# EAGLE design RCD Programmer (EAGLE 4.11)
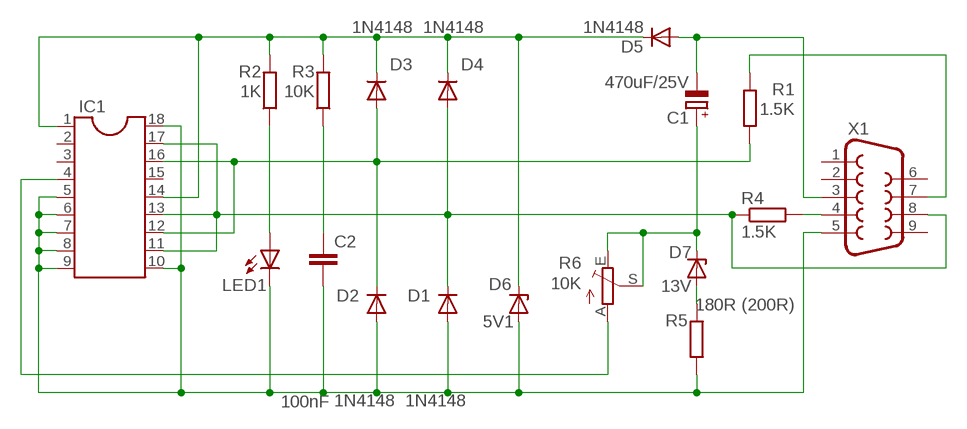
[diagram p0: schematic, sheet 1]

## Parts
C1  470uF/25V  CPOL-EUE3.5-8  [E3,5-8]
C2  100nF  C-EU025_050-025X075  [C025_050-025X075]
D1  1N4148  [DO35-10]
D2  1N4148  [DO35-10]
D3  1N4148  [DO35-10]
D4  1N4148  [DO35-10]
D5  1N4148  [DO35-10]
D6  5V1  BZX55  [DO35Z10]
D7  13V  BZX55  [DO35Z10]
IC1  DIL18S  [SOCKED-18]
LED1  LED3MM  [LED3MM]
R1  1.5K  R-EU_0207/10  [0207/10]
R2  1K  R-EU_0207/10  [0207/10]
R3  10K  R-EU_0207/10  [0207/10]
R4  1.5K  R-EU_0207/10  [0207/10]
R5  180R (200R)  R-EU_0207/10  [0207/10]
R6  10K  TRIM_EU-CA6V  [CA6V]
X1  F09HP  [F09HP]

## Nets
N$1: C2.2 D1.A D2.A D6.A IC1.5 IC1.6 IC1.7 IC1.8 IC1.9 IC1.10 IC1.18 LED1.K(C) R5.1 X1.5
N$2: D3.C D4.C D5.C D6.C IC1.1 IC1.14 R2.2 R3.2
N$3: D7.A R5.2
N$4: C1.+ D7.C R6.E R6.S
N$6: IC1.4 R6.A
N$7: C1.- D5.A X1.3
N$8: R4.2 X1.4
N$9: D1.C D4.A IC1.11 IC1.13 IC1.17 R4.1 X1.8
N$11: D2.C D3.A IC1.12 IC1.16 R1.1
N$12: C2.1 R3.1
N$13: LED1.A R2.1
N$14: R1.2 X1.7
Unconnected: IC1.2 IC1.3 IC1.15 X1.1 X1.2 X1.6 X1.9

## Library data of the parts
C1 = rcl:CPOL-EU: POLARIZED CAPACITOR, European symbol
C2 = rcl:C-EU: CAPACITOR, European symbol
D1-D5 = diode:1N4148: DIODE
D6 D7 = diode:BZX55: Z DIODE
IC1 = ic-package:DIL18: Dual In Line
LED1 = led:LED: LED
R1-R5 = rcl:R-EU_: RESISTOR, European symbol
R6 = pot:TRIM_EU-: POTENTIOMETER
X1 = con-subd:F09: SUB-D

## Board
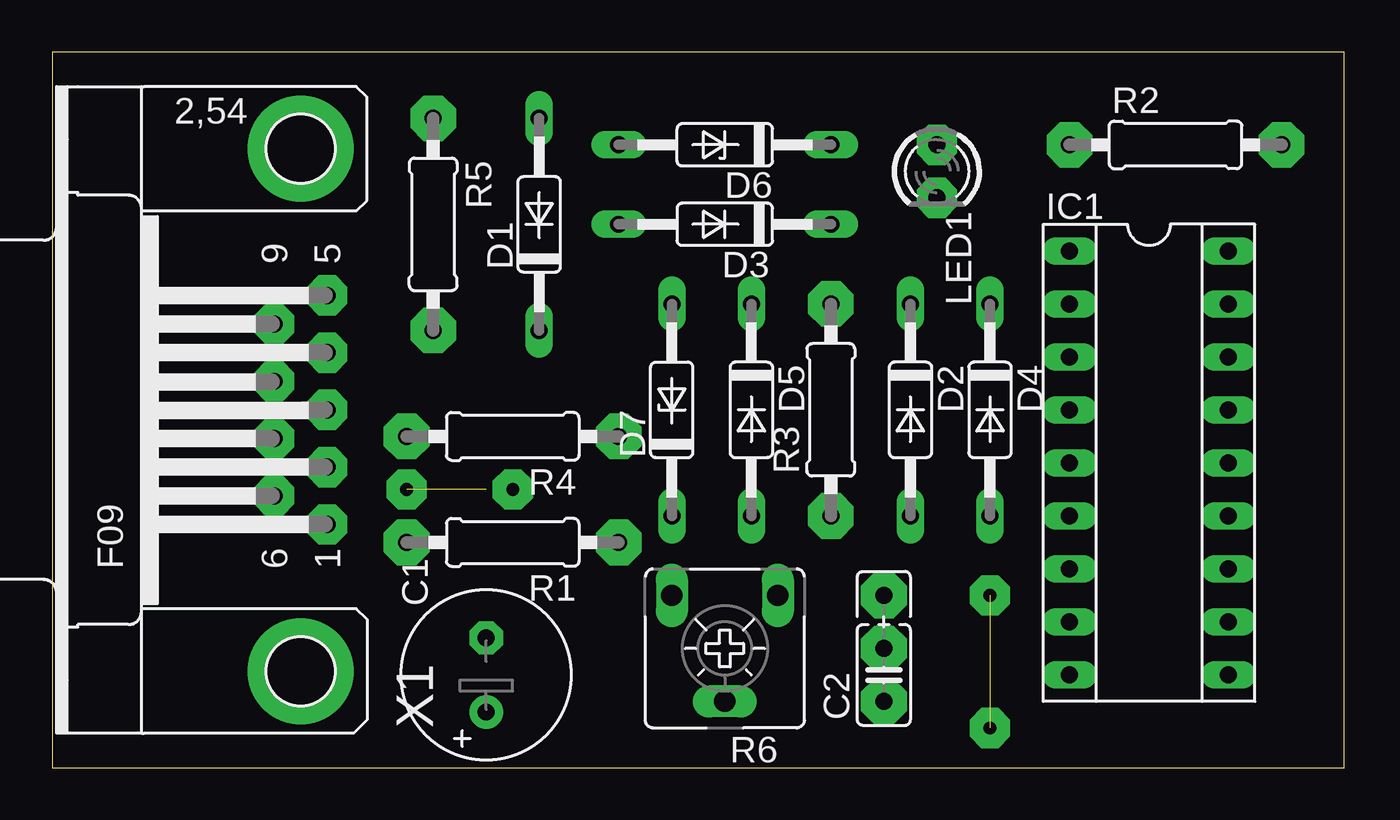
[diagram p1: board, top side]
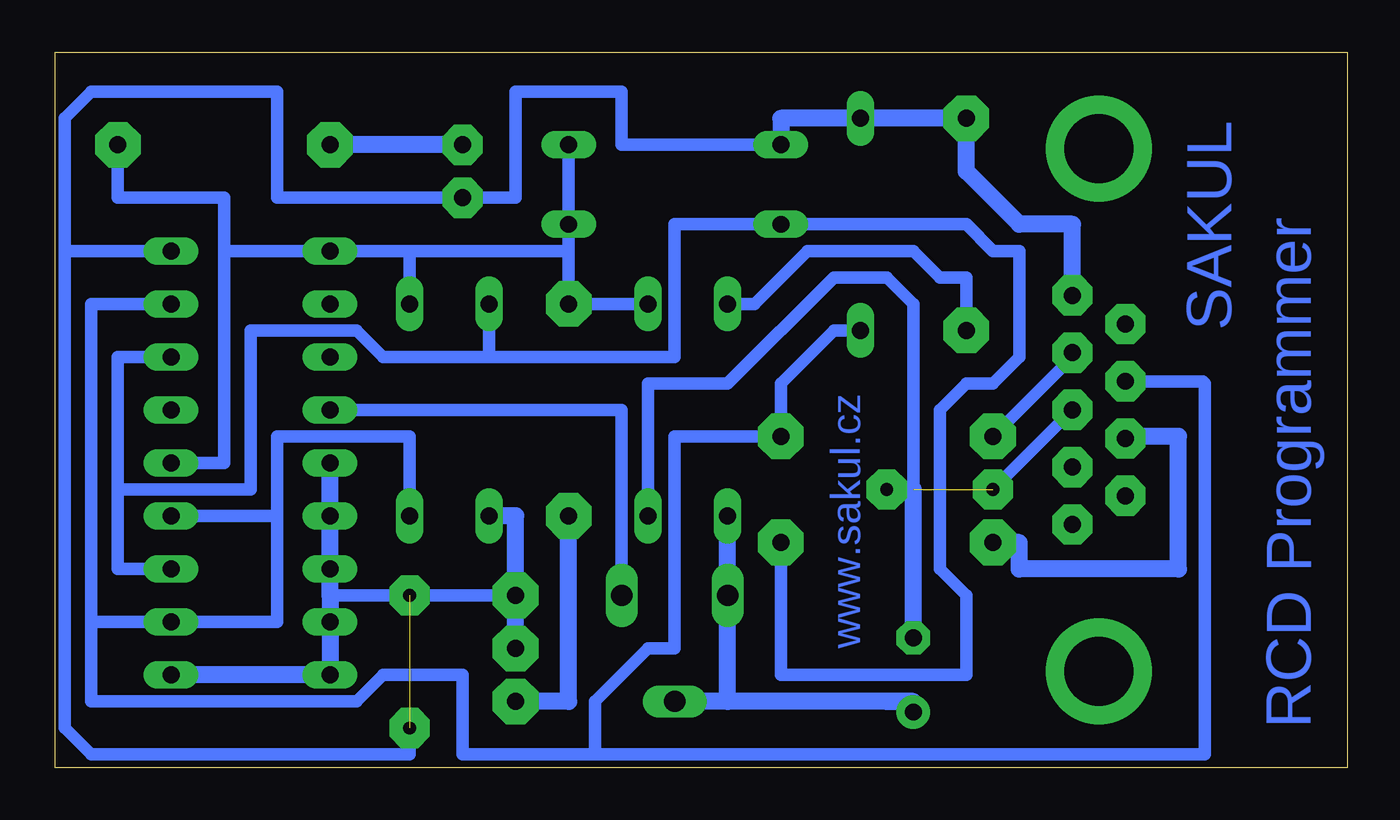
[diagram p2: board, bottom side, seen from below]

Size 61.9 x 34.28 mm. Coordinates in mm from the lower left corner, seen from the top.
Outline: 0,0 61.9,0 61.9,34.28 0,34.28 0,0
Copper layers (1*16): Top 0.035mm / dielectric 1.5mm / Bottom 0.035mm
Design rules "default": minimum track width 10mil, minimum drill 24mil, track to track 8mil, track to pad 8mil, pad to pad 8mil, via to via 8mil, smd to smd 8mil, copper to edge 40mil, drill to drill 8mil, minimum pad ring 10mil, minimum via ring 8mil, stop-mask expansion 4mil, vias tented up to drill 0mil, thermal gap 10mil

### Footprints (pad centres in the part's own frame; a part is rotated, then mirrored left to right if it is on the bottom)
E3,5-8 = drill 0.813 pad 1.6 round: + -1.778,0 | drill 0.813 pad 1.6 octagon: - 1.778,0
C025_050-025X075 = drill 0.813 pad 2.184 octagon: 1 -1.27,0; 2 1.27,0; 3 3.81,0
DO35-10 = drill 0.813 long: A 5.08,0; C -5.08,0
DO35Z10 = drill 0.813 long: A 5.08,0; C -5.08,0
SOCKED-18 = drill 0.813 long: 1 -10.16,-3.81; 2 -7.62,-3.81; 3 -5.08,-3.81; 4 -2.54,-3.81; 5 0,-3.81; 6 2.54,-3.81; 7 5.08,-3.81; 8 7.62,-3.81; 9 10.16,-3.81; 10 10.16,3.81; 11 7.62,3.81; 12 5.08,3.81; 13 2.54,3.81; 14 0,3.81; 15 -2.54,3.81; 16 -5.08,3.81; 17 -7.62,3.81; 18 -10.16,3.81
LED3MM = drill 0.813 pad 1.93 octagon: A -1.27,0; K 1.27,0
0207/10 = drill 0.813 pad 2.184 octagon: 1 -5.08,0; 2 5.08,0
CA6V = drill 1.016 long: A -2.54,-2.54; E 2.54,-2.54; S 0,2.54
F09HP = drill 0.813 pad 1.93 octagon: 1 -5.486,-1.27; 2 -2.743,-1.27; 3 0,-1.27; 4 2.743,-1.27; 5 5.486,-1.27; 6 -4.115,1.27; 7 -1.372,1.27; 8 1.372,1.27; 9 4.115,1.27 | drill 3.302 pad 5.08 round: G1 -12.522,0; G2 12.522,0

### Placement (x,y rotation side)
C1  20.79,4.44 90 top
C2  39.84,4.44 90 top
D1  23.33,26.03 90 top
D2  41.11,17.14 270 top
D3  32.22,26.03 180 top
D4  44.92,17.14 270 top
D5  33.49,17.14 270 top
D6  32.22,29.84 180 top
D7  29.68,17.14 90 top
IC1  52.54,14.6 270 top
LED1  42.38,28.57 270 top
R1  22.06,10.79 180 top
R2  53.81,29.84 0 top
R3  37.3,17.14 90 top
R4  22.06,15.87 180 top
R5  18.25,26.03 270 top
R6  32.22,5.71 180 top
X1  11.9,17.14 90 top

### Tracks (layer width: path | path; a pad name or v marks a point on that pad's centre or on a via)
N$1  (via drill 0.61 pad 1.93)  (1 unrouted)
  Bottom 0.61: D6.A 34.76,29.84 34.76,32.38 39.84,32.38 39.84,27.3 LED1.K 51.27,27.3 51.27,32.38 60.16,32.38 61.43,31.11 61.43,24.76 | 61.43,24.76 IC1.18 | 61.43,24.76 61.43,1.9 60.16,0.63 44.92,0.63 44.92,1.9 | 39.84,8.25 v44.92,8.25 48.73,8.25 IC1.9 IC1.10
  Bottom 0.813: IC1.10 IC1.9 IC1.8 48.73,8.25 IC1.7 IC1.6 IC1.5 | D2.A 39.84,12.06 39.84,8.25 C2.2 | X1.5 13.17,26.03 15.71,26.03 18.25,28.57 R5.1 D1.A 27.14,31.11 D6.A
N$2
  Bottom 0.61: D5.C R3.2 37.3,24.76 | 37.3,24.76 D3.C D6.C | 37.3,24.76 44.92,24.76 | 44.92,24.76 D4.C | 44.92,24.76 IC1.1 53.81,24.76 | 53.81,24.76 53.81,27.3 58.89,27.3 R2.2 | 53.81,24.76 53.81,14.6 IC1.14
N$3
  Bottom 0.61: R5.2 18.25,23.49 19.52,23.49 20.79,24.76 25.87,24.76 28.41,22.22 D7.A
N$4
  Bottom 0.813: 22.06,3.17 21.55,3.17 | 22.06,3.17 29.68,3.17 | 29.68,3.17 R6.S | 29.68,3.17 R6.E D7.C | C1.+ 20.79,3.17 22.06,3.17
N$5  (via drill 0.61 pad 1.93)
  other vias: 16.98,13.33
N$6
  Bottom 0.61: IC1.4 34.76,17.14 R6.A
N$7  (1 unrouted)
  Bottom 0.61: D5.A 33.49,18.41 29.68,18.41 24.6,23.49 22.06,23.49 20.79,22.22 20.79,13.33 22.06,13.33 | 16.98,13.33 X1.3
  Bottom 0.813: C1.- 20.79,13.33
N$8
  Bottom 0.61: X1.4 13.17,19.68 R4.2
N$9
  Bottom 0.406: 10.53,18.51 X1.8
  Bottom 0.61: D4.A 44.92,15.87 51.27,15.87 51.27,12.06 | D1.C 24.6,20.95 27.14,18.41 R4.1 32.22,15.87 32.22,5.71 33.49,5.71 36.03,3.17 36.03,0.63 | 51.27,12.06 IC1.13 | 51.27,12.06 51.27,6.98 IC1.11 60.16,6.98 | 60.16,6.98 60.16,22.22 IC1.17 | 10.53,18.51 6.92,18.51 6.82,18.41 6.82,0.63 36.03,0.63 | 36.03,0.63 42.38,0.63 42.38,4.44 46.19,4.44 47.46,3.17 60.16,3.17 60.16,6.98
N$10  (via drill 0.61 pad 1.93)
  other vias: 22.06,13.33
N$11
  Bottom 0.61: 41.11,19.68 D2.C | 41.11,19.68 32.22,19.68 32.22,26.03 D3.A 18.25,26.03 16.98,24.76 15.71,24.76 15.71,19.68 16.98,18.41 18.25,18.41 19.52,17.14 19.52,9.52 18.25,8.25 18.25,4.44 27.14,4.44 R1.1 | 41.11,19.68 46.19,19.68 47.46,20.95 52.54,20.95 52.54,13.33 58.89,13.33 | 58.89,13.33 58.89,9.52 IC1.12 | IC1.16 58.89,19.68 58.89,13.33
N$12
  Bottom 0.813: R3.1 37.3,3.17 C2.1
N$13
  Bottom 0.813: LED1.A R2.1
N$14
  Bottom 0.813: R1.2 15.71,10.79 15.71,9.52 8.09,9.52 8.09,15.87 10.63,15.87 X1.7
N$15  (via drill 0.61 pad 1.93)
  other vias: 44.92,1.9

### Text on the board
Bottom: SAKUL | www.sakul.cz | RCD Programmer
